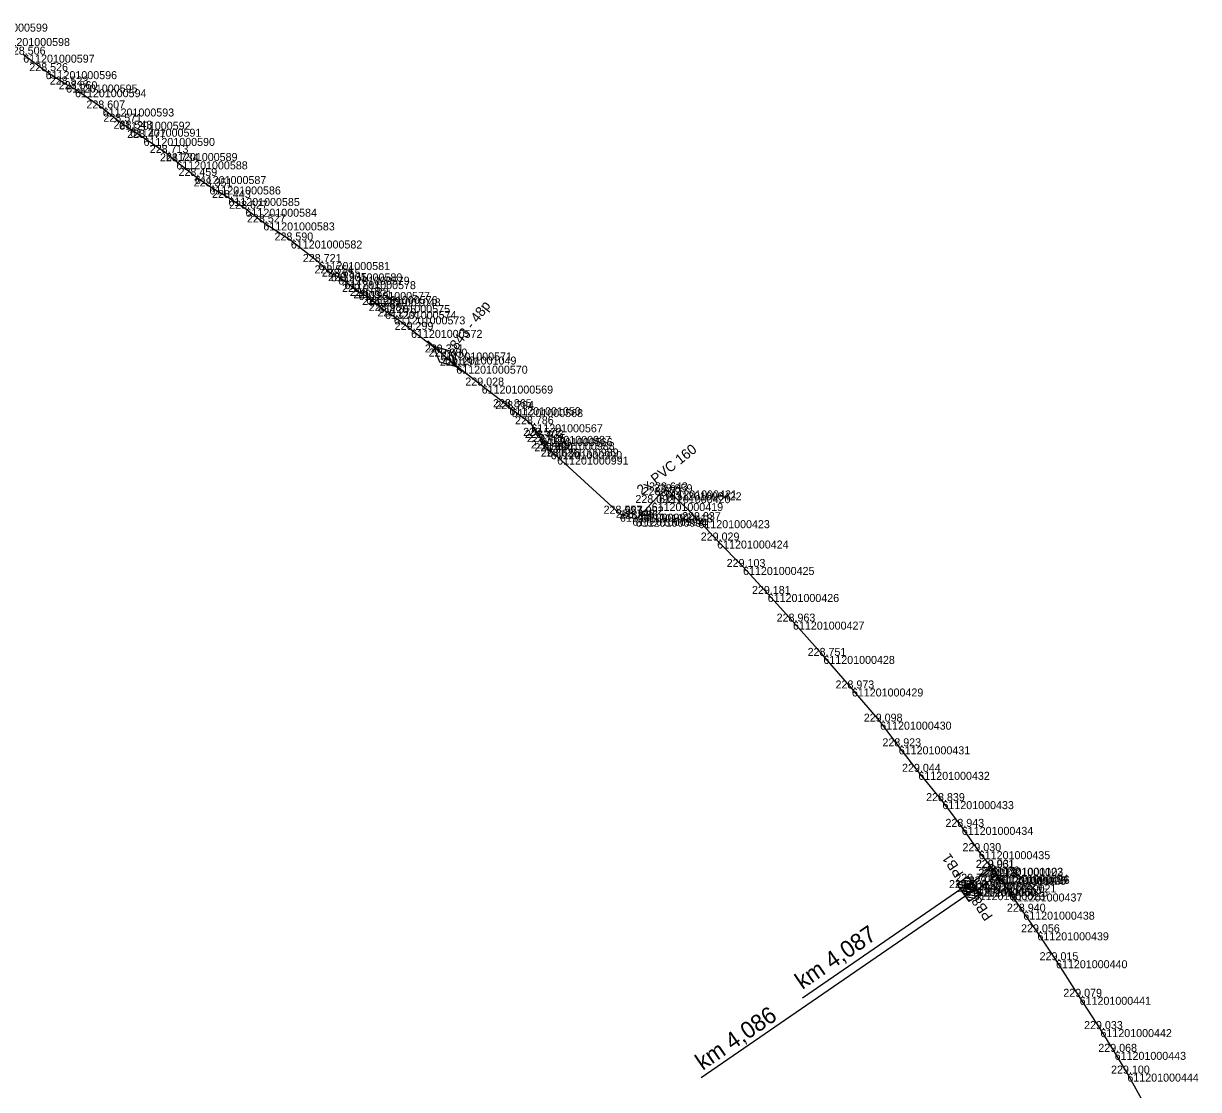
# Model space of a CAD drawing. Extents: x -771040 to -768909, y -1052366 to -1050115.
# Drawn here: x -769692.9 to -769516.7, y -1050384.6 to -1050224.8 of the extents above; entities that cross this region are included whole.
import ezdxf

# ---------------------------------------------------------------- set-up
doc = ezdxf.new("R2010")
doc.units = 0
for name, color, linetype in [('Vrstva 27', 7, 'Continuous'), ('Vrstva 28', 7, 'Continuous'), ('Vrstva 3', 7, 'Continuous'), ('Vrstva 35', 7, 'Continuous'), ('Vrstva 60', 7, 'Continuous'), ('Vrstva 61', 7, 'Continuous')]:
    doc.layers.add(name, color=color, linetype=linetype)

msp = doc.modelspace()

# ---------------------------------------------------------------- linework, layer by layer
at = {"layer": 'Vrstva 27'}
for p, q in [((-769547.75, -1050351.31), (-769547.69, -1050351.4)), ((-769547.28, -1050352.64), (-769547.22, -1050352.72))]:
    msp.add_line(p, q, dxfattribs=at)
for centre in [(-769547.72, -1050351.36), (-769547.25, -1050352.68)]:
    msp.add_circle(centre, 0.5, dxfattribs=at)
at = {"layer": 'Vrstva 28'}
for p, q in [((-769627.08, -1050277.07), (-769632.24, -1050272.37)), ((-769630.44, -1050275.58), (-769631.38, -1050273.15)), ((-769631.38, -1050273.15), (-769628.87, -1050273.86)), ((-769628.87, -1050273.86), (-769627.94, -1050276.28)), ((-769627.94, -1050276.28), (-769630.44, -1050275.58))]:
    msp.add_line(p, q, dxfattribs=at)
for points in [[(-769624.16, -1050279.07), (-769627.97, -1050276.09), (-769629.66, -1050274.72), (-769630.33, -1050274.11), (-769634.75, -1050270.72), (-769637.32, -1050268.7), (-769638.65, -1050267.91), (-769639.61, -1050267), (-769641.03, -1050265.99), (-769641.47, -1050265.65), (-769642.63, -1050265.04), (-769644.73, -1050263.42), (-769645.67, -1050262.75), (-769646.77, -1050262.26), (-769648.61, -1050260.56), (-769652.77, -1050257.33), (-769656.9, -1050254.62), (-769659.57, -1050252.57), (-769662.14, -1050250.96), (-769664.98, -1050249.23), (-769667.16, -1050247.67), (-769669.95, -1050245.47), (-769671.48, -1050244.22), (-769674.86, -1050241.96), (-769676.9, -1050240.58), (-769678.52, -1050239.53), (-769680.98, -1050237.55), (-769685.13, -1050234.66), (-769686.47, -1050233.96), (-769689.54, -1050231.95), (-769692.9, -1050229.48)], [(-769614.33, -1050288.49), (-769614.93, -1050287.54), (-769615.23, -1050286.93), (-769615.48, -1050286.61), (-769616.71, -1050284.87), (-769619.67, -1050282.59), (-769620.01, -1050282.31), (-769624.16, -1050279.07)], [(-769614.33, -1050288.49), (-769613.8, -1050288.91)], [(-769603.43, -1050298.27), (-769612.84, -1050289.71), (-769613.8, -1050288.91)], [(-769601.04, -1050299.02), (-769600.23, -1050298.38), (-769598.67, -1050296.67), (-769597.56, -1050295.49), (-769596.61, -1050294.78)], [(-769547.67, -1050351.32), (-769549.62, -1050348.84), (-769552.17, -1050345.2), (-769555.07, -1050341.34), (-769558.68, -1050336.95), (-769561.62, -1050333.13), (-769564.41, -1050329.43), (-769568.65, -1050324.46), (-769572.92, -1050319.58), (-769577.48, -1050314.44), (-769581.27, -1050310.3), (-769584.97, -1050306.25), (-769588.85, -1050302.29), (-769591.66, -1050299.24), (-769595.9, -1050295.06), (-769596.61, -1050294.78)], [(-769603.43, -1050298.27), (-769601.57, -1050298.87), (-769601.04, -1050299.02)], [(-769547.72, -1050351.36), (-769551.64, -1050354.38), (-769550.7, -1050353.43)], [(-769547.25, -1050352.68), (-769548.69, -1050353.82), (-769550.38, -1050354.98), (-769549.95, -1050354.44)], [(-769547.67, -1050351.32), (-769547.72, -1050351.36)], [(-769547.67, -1050351.32), (-769546.86, -1050352.34)], [(-769546.86, -1050352.34), (-769547.16, -1050352.62), (-769547.25, -1050352.68)], [(-769524.66, -1050386.93), (-769527.34, -1050382.17), (-769529.25, -1050378.91), (-769531.38, -1050375.5), (-769534.5, -1050370.66), (-769538.04, -1050365.18), (-769540.83, -1050361), (-769542.95, -1050357.91), (-769544.8, -1050355.18), (-769546.7, -1050352.54), (-769546.86, -1050352.34)]]:
    msp.add_lwpolyline(points, dxfattribs=at)
at = {"layer": 'Vrstva 3'}
for p, q in [((-769549.95, -1050354.44), (-769591.27, -1050382.82)), ((-769550.7, -1050353.43), (-769576.06, -1050370.86)), ((-769552.91, -1050353.74), (-769550.13, -1050354.26)), ((-769552.61, -1050354.18), (-769550.57, -1050354.56)), ((-769552.48, -1050353.44), (-769550.43, -1050353.82)), ((-769552.04, -1050353.14), (-769550.73, -1050353.38)), ((-769551.73, -1050354.45), (-769549.69, -1050354.83)), ((-769551.6, -1050352.84), (-769551.03, -1050352.95)), ((-769551.29, -1050354.15), (-769549.99, -1050354.39)), ((-769550.86, -1050353.85), (-769550.29, -1050353.95)), ((-769552.31, -1050354.62), (-769551.01, -1050354.86)), ((-769552.17, -1050354.75), (-769549.39, -1050355.27)), ((-769552.01, -1050355.05), (-769551.44, -1050355.16)), ((-769551.87, -1050355.19), (-769549.82, -1050355.57)), ((-769551.57, -1050355.62), (-769550.26, -1050355.87)), ((-769551.27, -1050356.06), (-769550.7, -1050356.17))]:
    msp.add_line(p, q, dxfattribs=at)
for points in [[(-769551.27, -1050352.61), (-769550.13, -1050354.26), (-769551.78, -1050355.39), (-769552.91, -1050353.74)], [(-769550.52, -1050353.62), (-769549.39, -1050355.27), (-769551.04, -1050356.4), (-769552.17, -1050354.75)]]:
    msp.add_lwpolyline(points, close=True, dxfattribs=at)
at = {"layer": 'Vrstva 35'}
msp.add_lwpolyline([(-769601.04, -1050299.02), (-769600.23, -1050298.38), (-769598.67, -1050296.67), (-769597.56, -1050295.49)], dxfattribs=at)
at = {"layer": 'Vrstva 60'}
for p, q in [((-769689.54, -1050231.95), (-769689.54, -1050231.95)), ((-769686.47, -1050233.96), (-769686.47, -1050233.96)), ((-769685.13, -1050234.66), (-769685.13, -1050234.66)), ((-769680.98, -1050237.55), (-769680.98, -1050237.55)), ((-769678.52, -1050239.53), (-769678.52, -1050239.53)), ((-769676.9, -1050240.58), (-769676.9, -1050240.58)), ((-769674.86, -1050241.96), (-769674.86, -1050241.96)), ((-769671.48, -1050244.22), (-769671.48, -1050244.22)), ((-769669.95, -1050245.47), (-769669.95, -1050245.47)), ((-769667.16, -1050247.67), (-769667.16, -1050247.67)), ((-769664.98, -1050249.23), (-769664.98, -1050249.23)), ((-769662.14, -1050250.96), (-769662.14, -1050250.96)), ((-769659.57, -1050252.57), (-769659.57, -1050252.57)), ((-769656.9, -1050254.62), (-769656.9, -1050254.62)), ((-769652.77, -1050257.33), (-769652.77, -1050257.33)), ((-769648.61, -1050260.56), (-769648.61, -1050260.56)), ((-769646.77, -1050262.26), (-769646.77, -1050262.26)), ((-769645.67, -1050262.75), (-769645.67, -1050262.75)), ((-769644.73, -1050263.42), (-769644.73, -1050263.42)), ((-769642.63, -1050265.04), (-769642.63, -1050265.04)), ((-769641.47, -1050265.65), (-769641.47, -1050265.65)), ((-769641.03, -1050265.99), (-769641.03, -1050265.99)), ((-769639.61, -1050267), (-769639.61, -1050267)), ((-769638.65, -1050267.91), (-769638.65, -1050267.91)), ((-769637.32, -1050268.7), (-769637.32, -1050268.7)), ((-769634.75, -1050270.72), (-769634.75, -1050270.72)), ((-769630.33, -1050274.11), (-769630.33, -1050274.11)), ((-769629.66, -1050274.72), (-769629.66, -1050274.72)), ((-769627.97, -1050276.09), (-769627.97, -1050276.09)), ((-769624.16, -1050279.07), (-769624.16, -1050279.07)), ((-769620.01, -1050282.31), (-769620.01, -1050282.31)), ((-769619.67, -1050282.59), (-769619.67, -1050282.59)), ((-769616.71, -1050284.87), (-769616.71, -1050284.87)), ((-769615.48, -1050286.61), (-769615.48, -1050286.61)), ((-769615.23, -1050286.93), (-769615.23, -1050286.93)), ((-769614.93, -1050287.54), (-769614.93, -1050287.54)), ((-769614.33, -1050288.49), (-769614.33, -1050288.49)), ((-769613.8, -1050288.91), (-769613.8, -1050288.91)), ((-769612.84, -1050289.71), (-769612.84, -1050289.71)), ((-769597.56, -1050295.49), (-769597.56, -1050295.49)), ((-769596.61, -1050294.78), (-769596.61, -1050294.78)), ((-769595.9, -1050295.06), (-769595.9, -1050295.06)), ((-769598.67, -1050296.67), (-769598.67, -1050296.67)), ((-769603.43, -1050298.27), (-769603.43, -1050298.27)), ((-769601.57, -1050298.87), (-769601.57, -1050298.87)), ((-769601.04, -1050299.02), (-769601.04, -1050299.02)), ((-769600.23, -1050298.38), (-769600.23, -1050298.38)), ((-769591.66, -1050299.24), (-769591.66, -1050299.24)), ((-769588.85, -1050302.29), (-769588.85, -1050302.29)), ((-769584.97, -1050306.25), (-769584.97, -1050306.25)), ((-769581.27, -1050310.3), (-769581.27, -1050310.3)), ((-769577.48, -1050314.44), (-769577.48, -1050314.44)), ((-769572.92, -1050319.58), (-769572.92, -1050319.58)), ((-769568.65, -1050324.46), (-769568.65, -1050324.46)), ((-769564.41, -1050329.43), (-769564.41, -1050329.43)), ((-769561.62, -1050333.13), (-769561.62, -1050333.13)), ((-769558.68, -1050336.95), (-769558.68, -1050336.95)), ((-769555.07, -1050341.34), (-769555.07, -1050341.34)), ((-769552.17, -1050345.2), (-769552.17, -1050345.2)), ((-769549.62, -1050348.84), (-769549.62, -1050348.84)), ((-769547.72, -1050351.36), (-769547.72, -1050351.36)), ((-769547.67, -1050351.32), (-769547.67, -1050351.32)), ((-769547.25, -1050352.68), (-769547.25, -1050352.68)), ((-769547.16, -1050352.62), (-769547.16, -1050352.62)), ((-769546.86, -1050352.34), (-769546.86, -1050352.34)), ((-769546.7, -1050352.54), (-769546.7, -1050352.54)), ((-769551.64, -1050354.38), (-769551.64, -1050354.38)), ((-769550.7, -1050353.43), (-769550.7, -1050353.43)), ((-769549.95, -1050354.44), (-769549.95, -1050354.44)), ((-769548.69, -1050353.82), (-769548.69, -1050353.82)), ((-769550.38, -1050354.98), (-769550.38, -1050354.98)), ((-769544.8, -1050355.18), (-769544.8, -1050355.18)), ((-769542.95, -1050357.91), (-769542.95, -1050357.91)), ((-769540.83, -1050361), (-769540.83, -1050361)), ((-769538.04, -1050365.18), (-769538.04, -1050365.18)), ((-769534.5, -1050370.66), (-769534.5, -1050370.66)), ((-769531.38, -1050375.5), (-769531.38, -1050375.5)), ((-769529.25, -1050378.91), (-769529.25, -1050378.91)), ((-769527.34, -1050382.17), (-769527.34, -1050382.17))]:
    msp.add_line(p, q, dxfattribs=at)

# ---------------------------------------------------------------- texts
at = {"layer": 'Vrstva 28'}
msp.add_text('843 - 48p', height=1.5, rotation=52.464, dxfattribs=at).set_placement((-769627.9, -1050273.82))
at = {"layer": 'Vrstva 3'}
for s, height, rotation, p in [('PB1', 1.5, 124.4892, (-769551.85, -1050352.15)), ('PB8', 1.5, 124.4892, (-769547.44, -1050358.6)), ('km 4,087', 2.5, 34.4892, (-769576.08, -1050369.65)), ('km 4,086', 2.5, 34.4892, (-769591.02, -1050381.77))]:
    msp.add_text(s, height=height, rotation=rotation, dxfattribs=at).set_placement(p)
at = {"layer": 'Vrstva 35'}
msp.add_text('2x PVC 160', height=1.5, rotation=38.4166, dxfattribs=at).set_placement((-769600.16, -1050295.54))
at = {"layer": 'Vrstva 60'}
for s, p in [('611201000599', (-769699.92, -1050226.03)), ('611201000598', (-769696.6, -1050228.19)), ('611201000597', (-769692.9, -1050230.68)), ('611201000596', (-769689.54, -1050233.15)), ('611201000595', (-769686.47, -1050235.16)), ('611201000594', (-769685.13, -1050235.86)), ('611201000593', (-769680.98, -1050238.75)), ('611201000592', (-769678.52, -1050240.73)), ('611201000591', (-769676.9, -1050241.78)), ('611201000590', (-769674.86, -1050243.16)), ('611201000589', (-769671.48, -1050245.42)), ('611201000588', (-769669.95, -1050246.67)), ('611201000587', (-769667.16, -1050248.87)), ('611201000586', (-769664.98, -1050250.43)), ('611201000585', (-769662.14, -1050252.16)), ('611201000584', (-769659.57, -1050253.77)), ('611201000583', (-769656.9, -1050255.82)), ('611201000582', (-769652.77, -1050258.53)), ('611201000581', (-769648.61, -1050261.76)), ('611201000580', (-769646.77, -1050263.46)), ('611201000579', (-769645.67, -1050263.95)), ('611201000578', (-769644.73, -1050264.62)), ('611201000577', (-769642.63, -1050266.24)), ('611201000576', (-769641.47, -1050266.85)), ('611201001048', (-769641.03, -1050267.19)), ('611201000575', (-769639.61, -1050268.2)), ('611201000574', (-769638.65, -1050269.11)), ('611201000573', (-769637.32, -1050269.9)), ('611201000572', (-769634.75, -1050271.92)), ('611201000571', (-769630.33, -1050275.31)), ('611201001049', (-769629.66, -1050275.92)), ('611201000570', (-769627.97, -1050277.29)), ('611201000569', (-769624.16, -1050280.27)), ('611201001050', (-769620.01, -1050283.51)), ('611201000568', (-769619.67, -1050283.79)), ('611201000567', (-769616.71, -1050286.07)), ('611201000987', (-769615.48, -1050287.81)), ('611201000566', (-769615.23, -1050288.13)), ('611201000988', (-769614.93, -1050288.74)), ('611201000989', (-769614.33, -1050289.69)), ('611201000990', (-769613.8, -1050290.11)), ('611201000991', (-769612.84, -1050290.91)), ('611201000420', (-769597.56, -1050296.69)), ('611201000421', (-769596.61, -1050295.98)), ('611201000422', (-769595.9, -1050296.26)), ('611201000419', (-769598.67, -1050297.87)), ('611201000992', (-769603.43, -1050299.47)), ('611201000993', (-769601.57, -1050300.07)), ('611201000994', (-769601.04, -1050300.22)), ('611201000418', (-769600.23, -1050299.58)), ('611201000423', (-769591.66, -1050300.44)), ('611201000424', (-769588.85, -1050303.49)), ('611201000425', (-769584.97, -1050307.45)), ('611201000426', (-769581.27, -1050311.5)), ('611201000427', (-769577.48, -1050315.64)), ('611201000428', (-769572.92, -1050320.78)), ('611201000429', (-769568.65, -1050325.66)), ('611201000430', (-769564.41, -1050330.63)), ('611201000431', (-769561.62, -1050334.33)), ('611201000432', (-769558.68, -1050338.15)), ('611201000433', (-769555.07, -1050342.54)), ('611201000434', (-769552.17, -1050346.4)), ('611201000435', (-769549.62, -1050350.04)), ('611201000022', (-769547.72, -1050352.56)), ('611201001103', (-769547.67, -1050352.52)), ('611201000020', (-769547.25, -1050353.88)), ('611201001105', (-769547.16, -1050353.82)), ('611201001104', (-769546.86, -1050353.54)), ('611201000436', (-769546.7, -1050353.74)), ('611201001159', (-769551.64, -1050355.58)), ('611201000024', (-769550.7, -1050354.63)), ('611201000025', (-769549.95, -1050355.64)), ('611201000021', (-769548.69, -1050355.02)), ('611201000023', (-769550.38, -1050356.18)), ('611201000437', (-769544.8, -1050356.38)), ('611201000438', (-769542.95, -1050359.1)), ('611201000439', (-769540.83, -1050362.2)), ('611201000440', (-769538.04, -1050366.38)), ('611201000441', (-769534.5, -1050371.86)), ('611201000442', (-769531.38, -1050376.7)), ('611201000443', (-769529.25, -1050380.11)), ('611201000444', (-769527.34, -1050383.37))]:
    msp.add_text(s, height=1.2, dxfattribs=at).set_placement(p)
at = {"layer": 'Vrstva 61'}
for s, p in [('228.506', (-769695.35, -1050229.48)), ('228.526', (-769691.99, -1050231.95)), ('228.523', (-769688.92, -1050233.96)), ('228.560', (-769687.58, -1050234.66)), ('228.607', (-769683.43, -1050237.55)), ('228.571', (-769680.88, -1050239.53)), ('228.543', (-769679.35, -1050240.58)), ('228.477', (-769677.31, -1050241.96)), ('228.713', (-769673.93, -1050244.22)), ('228.734', (-769672.4, -1050245.47)), ('228.459', (-769669.62, -1050247.67)), ('228.351', (-769667.34, -1050249.23)), ('228.443', (-769664.59, -1050250.96)), ('228.627', (-769662.02, -1050252.57)), ('228.527', (-769659.35, -1050254.62)), ('228.590', (-769655.22, -1050257.33)), ('228.721', (-769650.97, -1050260.56)), ('228.554', (-769649.22, -1050262.26)), ('228.655', (-769648.13, -1050262.75)), ('228.935', (-769647.18, -1050263.42)), ('229.015', (-769645.09, -1050265.04)), ('229.022', (-769643.92, -1050265.65)), ('228.971', (-769643.39, -1050265.99)), ('228.989', (-769642.07, -1050267)), ('228.987', (-769641.1, -1050267.91)), ('229.279', (-769639.78, -1050268.7)), ('229.299', (-769637.2, -1050270.72)), ('229.321', (-769632.68, -1050274.11)), ('229.380', (-769632.11, -1050274.72)), ('229.197', (-769630.42, -1050276.09)), ('229.028', (-769626.61, -1050279.07)), ('228.865', (-769622.46, -1050282.31)), ('228.794', (-769622.12, -1050282.59)), ('228.786', (-769619.16, -1050284.87)), ('228.572', (-769617.93, -1050286.61)), ('228.403', (-769617.68, -1050286.93)), ('228.435', (-769617.38, -1050287.54)), ('228.449', (-769616.78, -1050288.49)), ('228.494', (-769616.25, -1050288.91)), ('228.626', (-769615.29, -1050289.71)), ('228.672', (-769600.01, -1050295.49)), ('228.643', (-769599.06, -1050294.78)), ('228.859', (-769598.35, -1050295.06)), ('228.092', (-769601.11, -1050296.67)), ('228.557', (-769605.88, -1050298.27)), ('228.745', (-769604.03, -1050298.87)), ('228.686', (-769603.49, -1050299.02)), ('227.992', (-769602.68, -1050298.38)), ('228.837', (-769594.11, -1050299.24)), ('229.029', (-769591.31, -1050302.29)), ('229.103', (-769587.42, -1050306.25)), ('229.181', (-769583.63, -1050310.3)), ('228.963', (-769579.93, -1050314.44)), ('228.751', (-769575.28, -1050319.58)), ('228.973', (-769571.1, -1050324.46)), ('229.098', (-769566.86, -1050329.43)), ('228.923', (-769564.07, -1050333.13)), ('229.044', (-769561.13, -1050336.95)), ('228.839', (-769557.52, -1050341.34)), ('228.943', (-769554.62, -1050345.2)), ('229.030', (-769552.07, -1050348.84)), ('229.961', (-769550.08, -1050351.36)), ('229.031', (-769550.03, -1050351.32)), ('229.726', (-769553.15, -1050353.43)), ('229.676', (-769551.14, -1050353.82)), ('229.913', (-769549.7, -1050352.68)), ('229.373', (-769549.61, -1050352.62)), ('229.032', (-769549.31, -1050352.34)), ('229.032', (-769549.15, -1050352.54)), ('229.560', (-769554.09, -1050354.38)), ('229.499', (-769552.83, -1050354.98)), ('229.725', (-769552.41, -1050354.44)), ('228.983', (-769547.25, -1050355.18)), ('228.940', (-769545.4, -1050357.91)), ('229.056', (-769543.28, -1050361)), ('229.015', (-769540.5, -1050365.18)), ('229.079', (-769536.95, -1050370.66)), ('229.033', (-769533.83, -1050375.5)), ('229.068', (-769531.7, -1050378.91)), ('229.100', (-769529.79, -1050382.17))]:
    msp.add_text(s, height=1.2, dxfattribs=at).set_placement(p)

doc.saveas('drawing.dxf')
